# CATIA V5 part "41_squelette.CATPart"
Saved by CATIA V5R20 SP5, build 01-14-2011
Part number: 41_squelette
Publications: "diam_ext", "Point.4", "Point.6", "Point.7", "Plan.4", "Plan.5", "Plan.6"
Bounding box of the stored display mesh (mm): x 0 to 0, y 140.362 to 163.362, z -155.5 to -155.5
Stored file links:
  C:\Documents and Settings\anizard\Bureau\13\41_squelette.CATPart
  C:\Documents and Settings\anizard\Bureau\13\anizard.CATProduct
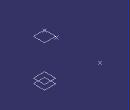
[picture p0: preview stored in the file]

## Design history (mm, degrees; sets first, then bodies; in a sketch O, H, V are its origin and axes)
Parameters
  diam_ext = 46 mm
Set1
  Plane1: linked copy from another document
  Point1: linked copy from another document
Body1 (main body)
  Point2: type OnPlane, Support Plane1, RefPoint Point1, H 0, V 0, Direction (1, 0, 0)
  Point3: (0, 5, 0), relative to Point2
  Point4: (0, 23 {= diam_ext /2}, 0), relative to Point2
  Plane2: type Offset, RefPlane Plane1, Offset 2, reversed
  Plane3: type Offset, RefPlane Plane2, Offset 15, reversed
  Plane4: type Offset, RefPlane Plane3, Offset 2, reversed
